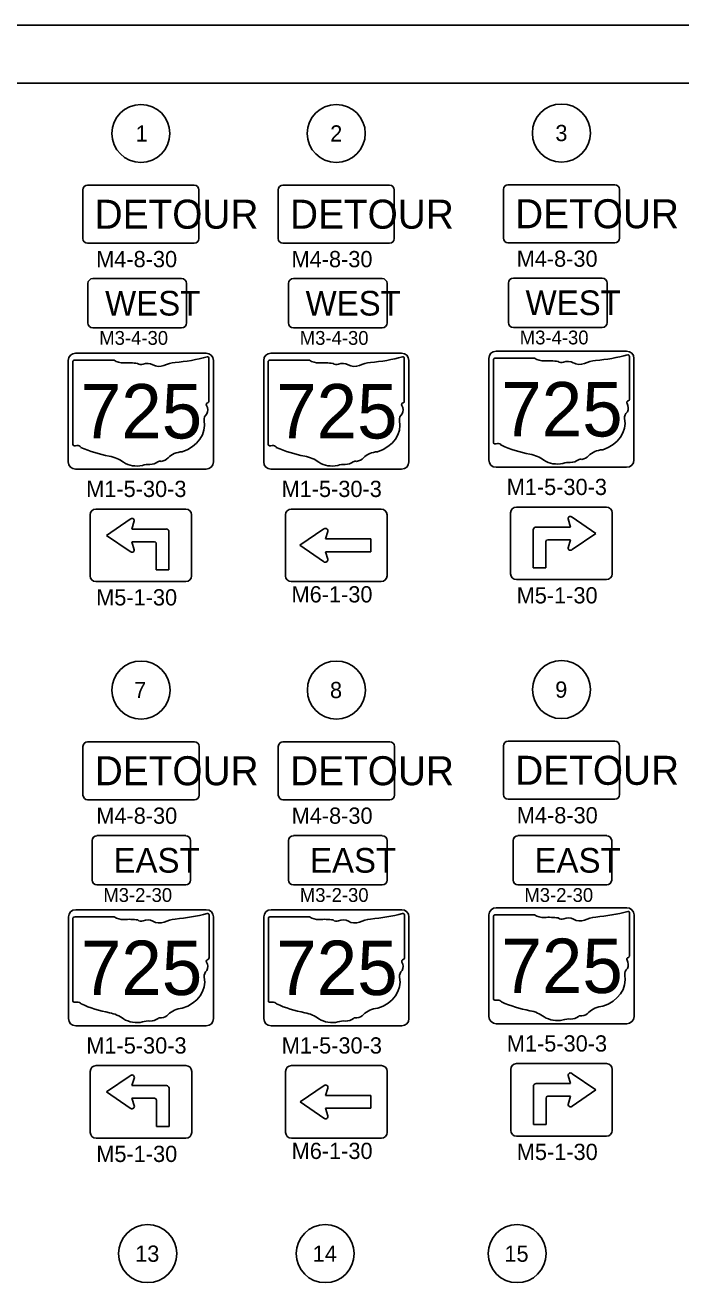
# Model space of a CAD drawing. Extents: x 1341221 to 1914484, y 79347 to 658398.
# Drawn here: x 1435873 to 1461287, y 609451 to 658398 of the extents above; entities that cross this region are included whole.
import ezdxf

# ---------------------------------------------------------------- set-up
doc = ezdxf.new("R2010")
doc.units = 0
for name, color, linetype in [('GM_X_County', 7, 'Continuous'), ('GM_X_County_Road_Text', 7, 'Continuous'), ('GM_X_Minor_Lake_Text', 7, 'Continuous'), ('GM_X_Minor_River', 7, 'Continuous'), ('GM_X_Minor_River_Text', 7, 'Continuous')]:
    doc.layers.add(name, color=color, linetype=linetype)

msp = doc.modelspace()

# ---------------------------------------------------------------- linework, layer by layer
at = {"layer": 'GM_X_County'}
for centre in [(1440356, 654203), (1447931, 654203), (1456659, 654220), (1440361, 632625), (1447935, 632625), (1456664, 632642)]:
    msp.add_circle(centre, 1125, dxfattribs=at)
at = {"layer": 'GM_X_County_Road_Text'}
for centre in [(1440619, 610773), (1447502, 610773), (1454943, 610773)]:
    msp.add_circle(centre, 1125, dxfattribs=at)
at = {"layer": 'GM_X_Minor_Lake_Text'}
msp.add_lwpolyline([(1347971, 656148), (1491971, 656148), (1491971, 561648), (1347971, 561648)], close=True, dxfattribs=at)
at = {"layer": 'GM_X_Minor_River'}
for p, q in [((1438494, 648577), (1441937, 648577)), ((1446268, 648577), (1449710, 648577)), ((1454798, 648594), (1458240, 648594)), ((1438303, 646856), (1438303, 648386)), ((1442128, 648386), (1442128, 646856)), ((1446077, 646856), (1446077, 648386)), ((1449902, 648386), (1449902, 646856)), ((1454606, 646873), (1454606, 648403)), ((1458431, 648403), (1458431, 646873)), ((1441937, 646665), (1438494, 646665)), ((1449710, 646665), (1446268, 646665)), ((1458240, 646682), (1454798, 646682)), ((1437719, 645353), (1437719, 642151)), ((1439315, 645408), (1437771, 645408)), ((1442992, 643813), (1442992, 645488)), ((1445294, 645353), (1445294, 642151)), ((1446890, 645408), (1445346, 645408)), ((1450567, 643813), (1450567, 645488)), ((1454022, 645431), (1454022, 642229)), ((1455618, 645486), (1454074, 645486)), ((1459295, 643890), (1459295, 645565)), ((1442992, 643813), (1442992, 643813)), ((1450566, 643813), (1450567, 643813)), ((1459295, 643891), (1459295, 643890)), ((1438387, 637053), (1438387, 639416)), ((1438612, 639641), (1442099, 639641)), ((1442324, 639416), (1442324, 637053)), ((1445962, 639416), (1445962, 637053)), ((1449674, 639641), (1446187, 639641)), ((1449675, 639641), (1449674, 639641)), ((1449899, 637053), (1449899, 639416)), ((1454690, 639493), (1454690, 637131)), ((1458403, 639718), (1454915, 639718)), ((1457010, 638945), (1456917, 639261)), ((1457077, 639328), (1457995, 638699)), ((1458628, 637131), (1458628, 639493)), ((1439938, 639250), (1439020, 638621)), ((1440004, 638867), (1440098, 639184)), ((1441340, 638867), (1440004, 638867)), ((1441340, 638867), (1441340, 638867)), ((1446524, 638235), (1447455, 638874)), ((1447598, 638769), (1447509, 638481)), ((1455569, 637363), (1455569, 638839)), ((1455674, 638945), (1457010, 638945)), ((1455674, 638945), (1455674, 638945)), ((1439020, 638621), (1439938, 637992)), ((1440098, 638059), (1440004, 638375)), ((1440004, 638375), (1440883, 638375)), ((1440953, 638305), (1440953, 637285)), ((1441446, 637285), (1441446, 638762)), ((1447509, 638481), (1449266, 638481)), ((1449266, 638481), (1449266, 637988)), ((1456061, 638382), (1456061, 637363)), ((1457010, 638452), (1456131, 638452)), ((1456917, 638136), (1457010, 638452)), ((1457995, 638699), (1457077, 638070)), ((1447442, 637606), (1446524, 638235)), ((1449266, 637988), (1447509, 637988)), ((1447509, 637988), (1447598, 637700)), ((1456061, 637363), (1455569, 637363)), ((1442099, 636828), (1438612, 636828)), ((1440953, 637285), (1441446, 637285)), ((1440953, 637285), (1441446, 637285)), ((1446187, 636828), (1449674, 636828)), ((1454915, 636906), (1458403, 636906)), ((1438461, 625258), (1438461, 626788)), ((1438652, 626979), (1442094, 626979)), ((1442286, 626788), (1442286, 625258)), ((1446079, 625258), (1446079, 626788)), ((1446270, 626979), (1449712, 626979)), ((1449904, 626788), (1449904, 625258)), ((1454785, 625258), (1454785, 626788)), ((1454976, 626979), (1458418, 626979)), ((1458610, 626788), (1458610, 625258)), ((1442094, 625066), (1438652, 625066)), ((1449712, 625066), (1446270, 625066)), ((1458418, 625066), (1454976, 625066)), ((1437724, 623776), (1437724, 620574)), ((1439320, 623831), (1437776, 623831)), ((1442997, 622235), (1442997, 623910)), ((1445298, 623776), (1445298, 620574)), ((1446895, 623831), (1445350, 623831)), ((1450572, 622235), (1450572, 623910)), ((1454027, 623853), (1454027, 620651)), ((1455623, 623908), (1454079, 623908)), ((1459300, 622313), (1459300, 623988)), ((1442996, 622235), (1442997, 622235)), ((1450571, 622235), (1450572, 622235)), ((1459300, 622313), (1459300, 622313)), ((1438392, 615476), (1438392, 617838)), ((1438617, 618063), (1442104, 618063)), ((1442329, 617838), (1442329, 615476)), ((1445967, 617838), (1445967, 615476)), ((1449679, 618063), (1446192, 618063)), ((1449679, 618063), (1449679, 618063)), ((1449904, 615476), (1449904, 617838)), ((1454695, 617916), (1454695, 615553)), ((1458408, 618141), (1454920, 618141)), ((1457082, 617750), (1458000, 617121)), ((1458633, 615553), (1458633, 617916)), ((1439943, 617672), (1439025, 617043)), ((1440009, 617289), (1440103, 617606)), ((1441345, 617289), (1440009, 617289)), ((1441345, 617289), (1441345, 617289)), ((1446529, 616657), (1447460, 617297)), ((1455574, 615785), (1455574, 617262)), ((1455679, 617367), (1457015, 617367)), ((1455679, 617367), (1455679, 617367)), ((1457015, 617367), (1456921, 617684)), ((1439025, 617043), (1439943, 616415)), ((1440103, 616481), (1440009, 616797)), ((1440009, 616797), (1440888, 616797)), ((1441451, 615707), (1441451, 617184)), ((1447603, 617192), (1447513, 616903)), ((1447513, 616903), (1449271, 616903)), ((1449271, 616903), (1449271, 616410)), ((1456066, 616805), (1456066, 615785)), ((1457015, 616875), (1456136, 616875)), ((1456921, 616559), (1457015, 616875)), ((1458000, 617121), (1457082, 616492)), ((1440958, 616727), (1440958, 615707)), ((1447447, 616028), (1446529, 616657)), ((1449271, 616410), (1447513, 616410)), ((1447513, 616410), (1447603, 616122)), ((1456066, 615785), (1455574, 615785)), ((1440958, 615707), (1441451, 615707)), ((1440958, 615707), (1441451, 615707)), ((1454920, 615328), (1458408, 615328)), ((1442104, 615251), (1438617, 615251)), ((1446192, 615251), (1449679, 615251))]:
    msp.add_line(p, q, dxfattribs=at)
for points in [[(1438106, 652018), (1438106, 650128)], [(1442426, 652198), (1438286, 652198)], [(1442606, 650128), (1442606, 652018)], [(1445681, 652018), (1445681, 650128)], [(1450001, 652198), (1445861, 652198)], [(1450181, 650128), (1450181, 652018)], [(1454409, 652035), (1454409, 650145)], [(1458729, 652215), (1454589, 652215)], [(1458909, 650145), (1458909, 652035)], [(1438286, 649948), (1442426, 649948)], [(1445861, 649948), (1450001, 649948)], [(1454589, 649965), (1458729, 649965)], [(1437824, 645685), (1442887, 645685)], [(1445399, 645685), (1450462, 645685)], [(1454128, 645762), (1459190, 645762)], [(1437543, 641466), (1437543, 645403)], [(1443168, 645403), (1443168, 641466)], [(1445118, 641466), (1445118, 645403)], [(1450743, 645403), (1450743, 641466)], [(1453846, 641543), (1453846, 645481)], [(1459471, 645481), (1459471, 641543)], [(1459190, 641262), (1454128, 641262)], [(1442887, 641184), (1437824, 641184)], [(1450462, 641184), (1445399, 641184)], [(1442431, 630620), (1438291, 630620)], [(1450005, 630620), (1445865, 630620)], [(1454414, 630458), (1454414, 628568)], [(1458734, 630638), (1454594, 630638)], [(1458914, 628568), (1458914, 630458)], [(1438111, 630440), (1438111, 628550)], [(1442611, 628550), (1442611, 630440)], [(1445685, 630440), (1445685, 628550)], [(1450185, 628550), (1450185, 630440)], [(1438291, 628370), (1442431, 628370)], [(1445865, 628370), (1450005, 628370)], [(1454594, 628388), (1458734, 628388)], [(1437829, 624107), (1442892, 624107)], [(1445404, 624107), (1450467, 624107)], [(1454133, 624184), (1459195, 624184)], [(1437548, 619888), (1437548, 623825)], [(1443173, 623825), (1443173, 619888)], [(1445123, 619888), (1445123, 623825)], [(1450748, 623825), (1450748, 619888)], [(1453851, 619966), (1453851, 623903)], [(1459476, 623903), (1459476, 619966)], [(1459195, 619684), (1454133, 619684)], [(1442892, 619607), (1437829, 619607)], [(1450467, 619607), (1445404, 619607)]]:
    msp.add_lwpolyline(points, dxfattribs=at)
for centre, radius, start, end in [((1438286, 652018), 180, 90, 180), ((1442426, 652018), 180, 0, 90), ((1445861, 652018), 180, 90, 180), ((1450001, 652018), 180, 0, 90), ((1454589, 652035), 180, 90, 180), ((1458729, 652035), 180, 0, 90), ((1438286, 650128), 180, 180, 270), ((1442426, 650128), 180, 270, 0), ((1445861, 650128), 180, 180, 270), ((1450001, 650128), 180, 270, 0), ((1454589, 650145), 180, 180, 270), ((1458729, 650145), 180, 270, 0), ((1438494, 648386), 191, 90, 180), ((1441937, 648386), 191, 0, 90), ((1446268, 648386), 191, 90, 180), ((1449710, 648386), 191, 0, 90), ((1454798, 648403), 191, 90, 180), ((1458240, 648403), 191, 0, 90), ((1438494, 646856), 191, 180, 270), ((1441937, 646856), 191, 270, 0), ((1446268, 646856), 191, 180, 270), ((1449710, 646856), 191, 270, 0), ((1454798, 646873), 191, 180, 270), ((1458240, 646873), 191, 270, 0), ((1437824, 645403), 281, 90, 180), ((1442887, 645403), 281, 0, 90), ((1445399, 645403), 281, 90, 180), ((1450462, 645403), 281, 0, 90), ((1454128, 645481), 281, 90, 180), ((1459190, 645481), 281, 0, 90), ((1437824, 641466), 281, 180, 270), ((1442887, 641466), 281, 270, 0), ((1445399, 641466), 281, 180, 270), ((1450462, 641466), 281, 270, 0), ((1454128, 641543), 281, 180, 270), ((1459190, 641543), 281, 270, 0), ((1438612, 639416), 225, 90, 180), ((1440004, 639184), 93.8, 0.0017, 134.9999), ((1442099, 639416), 225, 0, 90), ((1446187, 639416), 225, 90, 180), ((1449674, 639416), 225, 0, 90), ((1454915, 639493), 225, 90, 180), ((1457010, 639261), 93.8, 45.0001, 179.9983), ((1458403, 639493), 225, 0, 90), ((1441340, 638762), 106, 0, 90), ((1447509, 638797), 93.8, 342.7954, 124.5888), ((1455674, 638839), 106, 90, 180), ((1440883, 638305), 70.2, 0, 90), ((1456132, 638382), 70.2, 90, 180), ((1440004, 638059), 93.8, 225.0001, 0.0017), ((1457010, 638136), 93.8, 179.9983, 314.9999), ((1447509, 637672), 93.8, 224.9904, 17.2046), ((1438612, 637053), 225, 180, 270), ((1442099, 637053), 225, 270, 360), ((1446187, 637053), 225, 180, 270), ((1449674, 637053), 225, 270, 0), ((1454915, 637131), 225, 180, 270), ((1458403, 637131), 225, 270, 0), ((1438291, 630440), 180, 90, 180), ((1442431, 630440), 180, 0, 90), ((1445865, 630440), 180, 90, 180), ((1450005, 630440), 180, 0, 90), ((1454594, 630458), 180, 90, 180), ((1458734, 630458), 180, 0, 90), ((1438291, 628550), 180, 180, 270), ((1442431, 628550), 180, 270, 0), ((1445865, 628550), 180, 180, 270), ((1450005, 628550), 180, 270, 0), ((1454594, 628568), 180, 180, 270), ((1458734, 628568), 180, 270, 0), ((1438652, 626787), 191, 90, 180), ((1442094, 626787), 191, 0, 90), ((1446270, 626787), 191, 90, 180), ((1449712, 626787), 191, 0, 90), ((1454976, 626787), 191, 90, 180), ((1458418, 626787), 191, 0, 90), ((1438652, 625257), 191, 180, 270), ((1442094, 625257), 191, 270, 0), ((1446270, 625257), 191, 180, 270), ((1449712, 625257), 191, 270, 0), ((1454976, 625257), 191, 180, 270), ((1458418, 625257), 191, 270, 0), ((1437829, 623825), 281, 90, 180), ((1442892, 623825), 281, 0, 90), ((1445404, 623825), 281, 90, 180), ((1450467, 623825), 281, 0, 90), ((1454133, 623903), 281, 90, 180), ((1459195, 623903), 281, 0, 90), ((1437829, 619888), 281, 180, 270), ((1442892, 619888), 281, 270, 0), ((1445404, 619888), 281, 180, 270), ((1450467, 619888), 281, 270, 0), ((1454133, 619966), 281, 180, 270), ((1459195, 619966), 281, 270, 0), ((1438617, 617838), 225, 90, 180), ((1442104, 617838), 225, 0, 90), ((1446192, 617838), 225, 90, 180), ((1449679, 617838), 225, 0, 90), ((1454920, 617916), 225, 90, 180), ((1457015, 617684), 93.8, 45.0001, 179.9983), ((1458408, 617916), 225, 0, 90), ((1440009, 617606), 93.8, 0.0017, 134.9999), ((1441345, 617184), 106, 0, 90), ((1447514, 617219), 93.8, 342.7954, 124.5888), ((1455679, 617261), 106, 90, 180), ((1440888, 616727), 70.2, 0, 90), ((1456136, 616804), 70.2, 90, 180), ((1440009, 616481), 93.8, 225.0001, 0.0017), ((1457015, 616559), 93.8, 179.9983, 314.9999), ((1447514, 616094), 93.8, 224.9904, 17.2046), ((1438617, 615476), 225, 180, 270), ((1442104, 615476), 225, 270, 360), ((1446192, 615476), 225, 180, 270), ((1449679, 615476), 225, 270, 0), ((1454920, 615553), 225, 180, 270), ((1458408, 615553), 225, 270, 0)]:
    msp.add_arc(centre, radius, start, end, dxfattribs=at)
for centre, major_axis, start_param, end_param in [((1457417, 649851), (5592, 0), 4.814394, 5.042369), ((1459237, 645572), (58.7, 0), 6.141152, 7.989035), ((1437779, 645360), (61.1, 0), 1.712693, 3.28349), ((1439683, 645780), (593, 0), 4.042523, 4.731795), ((1439879, 643611), (2127, 0), 1.404758, 1.657858), ((1440362, 645377), (171, 0), 3.836095, 5.185415), ((1440613, 645007), (355, 0), 0.950623, 2.079405), ((1441072, 645514), (428, 0), 4.081561, 5.145723), ((1441827, 644430), (1125, 0), 1.699011, 2.107814), ((1441114, 649774), (5592, 0), 4.814394, 5.042369), ((1442934, 645495), (58.7, 0), 6.141152, 7.989035), ((1445354, 645360), (61.1, 0), 1.712693, 3.28349), ((1447258, 645780), (593, 0), 4.042523, 4.731795), ((1447454, 643611), (2127, 0), 1.404758, 1.657858), ((1447937, 645377), (171, 0), 3.836095, 5.185415), ((1448188, 645007), (355, 0), 0.950623, 2.079405), ((1448647, 645514), (428, 0), 4.081561, 5.145723), ((1449402, 644430), (1125, 0), 1.699011, 2.107814), ((1448689, 649774), (5592, 0), 4.814394, 5.042369), ((1450508, 645495), (58.7, 0), 6.141152, 7.989035), ((1454083, 645438), (61.1, 0), 1.712693, 3.28349), ((1455986, 645858), (593, 0), 4.042523, 4.731795), ((1456183, 643688), (2127, 0), 1.404758, 1.657858), ((1456666, 645454), (171, 0), 3.836095, 5.185415), ((1456916, 645084), (355, 0), 0.950623, 2.079405), ((1457375, 645592), (428, 0), 4.081561, 5.145723), ((1458130, 644508), (1125, 0), 1.699011, 2.107814), ((1442979, 643690), (90.9, 0), 1.883978, 3.671073), ((1442930, 643806), (62.8, 0), 5.05454, 6.418171), ((1450553, 643690), (90.9, 0), 1.883978, 3.671073), ((1450504, 643806), (62.8, 0), 5.05454, 6.418171), ((1459282, 643767), (90.9, 0), 1.883978, 3.671073), ((1458704, 643556), (545, 0), 5.934695, 6.695948), ((1459233, 643884), (62.8, 0), 5.05454, 6.418171), ((1443203, 643112), (397, 0), 2.387724, 3.262537), ((1442401, 643478), (545, 0), 5.934695, 6.695948), ((1450777, 643112), (397, 0), 2.387724, 3.262537), ((1449975, 643478), (545, 0), 5.934695, 6.695948), ((1459506, 643190), (397, 0), 2.387724, 3.262537), ((1441427, 642899), (1399, 0), 5.101752, 6.440018), ((1449002, 642899), (1399, 0), 5.101752, 6.440018), ((1457730, 642976), (1399, 0), 5.101752, 6.440018), ((1454083, 642222), (61.6, 0), 3.00124, 4.508301), ((1437780, 642144), (61.6, 0), 3.00124, 4.508301), ((1437789, 642472), (470, 0), 4.665946, 4.897461), ((1437885, 641967), (170, 0), 0.519207, 1.627899), ((1440027, 644843), (4038, 0), 4.195997, 4.488961), ((1442017, 641252), (766, 0), 1.647645, 2.488434), ((1445355, 642144), (61.6, 0), 3.00124, 4.508301), ((1445364, 642472), (470, 0), 4.665946, 4.897461), ((1445460, 641967), (170, 0), 0.519207, 1.627899), ((1447601, 644843), (4038, 0), 4.195997, 4.488961), ((1449592, 641252), (766, 0), 1.647645, 2.488434), ((1454092, 642550), (470, 0), 4.665946, 4.897461), ((1454189, 642044), (170, 0), 0.519207, 1.627899), ((1456330, 644921), (4038, 0), 4.195997, 4.488961), ((1455126, 640791), (1264, 0), 0.823519, 1.323587), ((1457349, 641919), (452, 0), 4.937069, 5.64225), ((1458320, 641330), (766, 0), 1.647645, 2.488434), ((1438823, 640713), (1264, 0), 0.823519, 1.323587), ((1440189, 641951), (802, 0), 4.026481, 4.996735), ((1440652, 640844), (659, 0), 1.495662, 1.94098), ((1440711, 641711), (427, 0), 4.691044, 5.507374), ((1441097, 641401), (120, 0), 1.147584, 2.315152), ((1441046, 641841), (452, 0), 4.937069, 5.64225), ((1446397, 640713), (1264, 0), 0.823519, 1.323587), ((1447764, 641951), (802, 0), 4.026481, 4.996735), ((1448227, 640844), (659, 0), 1.495662, 1.94098), ((1448286, 641711), (427, 0), 4.691044, 5.507374), ((1448672, 641401), (120, 0), 1.147584, 2.315152), ((1448621, 641841), (452, 0), 4.937069, 5.64225), ((1456492, 642028), (802, 0), 4.026481, 4.996735), ((1456956, 640921), (659, 0), 1.495662, 1.94098), ((1457014, 641789), (427, 0), 4.691044, 5.507374), ((1457401, 641479), (120, 0), 1.147584, 2.315152), ((1437784, 623782), (61.1, 0), 1.712693, 3.28349), ((1439688, 624202), (593, 0), 4.042523, 4.731795), ((1439884, 622033), (2127, 0), 1.404758, 1.657858), ((1440367, 623799), (171, 0), 3.836095, 5.185415), ((1440618, 623429), (355, 0), 0.950623, 2.079405), ((1441077, 623936), (428, 0), 4.081561, 5.145723), ((1441832, 622853), (1125, 0), 1.699011, 2.107814), ((1441119, 628196), (5592, 0), 4.814394, 5.042369), ((1442939, 623917), (58.7, 0), 6.141152, 7.989035), ((1445359, 623782), (61.1, 0), 1.712693, 3.28349), ((1447262, 624202), (593, 0), 4.042523, 4.731795), ((1447459, 622033), (2127, 0), 1.404758, 1.657858), ((1447942, 623799), (171, 0), 3.836095, 5.185415), ((1448193, 623429), (355, 0), 0.950623, 2.079405), ((1448652, 623936), (428, 0), 4.081561, 5.145723), ((1449407, 622853), (1125, 0), 1.699011, 2.107814), ((1448693, 628196), (5592, 0), 4.814394, 5.042369), ((1450513, 623917), (58.7, 0), 6.141152, 7.989035), ((1454087, 623860), (61.1, 0), 1.712693, 3.28349), ((1455991, 624280), (593, 0), 4.042523, 4.731795), ((1456187, 622111), (2127, 0), 1.404758, 1.657858), ((1456670, 623877), (171, 0), 3.836095, 5.185415), ((1456921, 623507), (355, 0), 0.950623, 2.079405), ((1457380, 624014), (428, 0), 4.081561, 5.145723), ((1458135, 622930), (1125, 0), 1.699011, 2.107814), ((1457422, 628274), (5592, 0), 4.814394, 5.042369), ((1459242, 623995), (58.7, 0), 6.141152, 7.989035), ((1442983, 622112), (90.9, 0), 1.883978, 3.671073), ((1442934, 622229), (62.8, 0), 5.05454, 6.418171), ((1450558, 622112), (90.9, 0), 1.883978, 3.671073), ((1450509, 622229), (62.8, 0), 5.05454, 6.418171), ((1459287, 622190), (90.9, 0), 1.883978, 3.671073), ((1458709, 621978), (545, 0), 5.934695, 6.695948), ((1459238, 622306), (62.8, 0), 5.05454, 6.418171), ((1443207, 621534), (397, 0), 2.387724, 3.262537), ((1442405, 621900), (545, 0), 5.934695, 6.695948), ((1450782, 621534), (397, 0), 2.387724, 3.262537), ((1449980, 621900), (545, 0), 5.934695, 6.695948), ((1459511, 621612), (397, 0), 2.387724, 3.262537), ((1441432, 621321), (1399, 0), 5.101752, 6.440018), ((1449007, 621321), (1399, 0), 5.101752, 6.440018), ((1457735, 621399), (1399, 0), 5.101752, 6.440018), ((1437785, 620567), (61.6, 0), 3.00124, 4.508301), ((1437794, 620894), (470, 0), 4.665946, 4.897461), ((1437890, 620389), (170, 0), 0.519207, 1.627899), ((1440031, 623266), (4038, 0), 4.195997, 4.488961), ((1442022, 619675), (766, 0), 1.647645, 2.488434), ((1445359, 620567), (61.6, 0), 3.00124, 4.508301), ((1445369, 620894), (470, 0), 4.665946, 4.897461), ((1445465, 620389), (170, 0), 0.519207, 1.627899), ((1447606, 623266), (4038, 0), 4.195997, 4.488961), ((1449596, 619675), (766, 0), 1.647645, 2.488434), ((1454088, 620644), (61.6, 0), 3.00124, 4.508301), ((1454097, 620972), (470, 0), 4.665946, 4.897461), ((1454193, 620467), (170, 0), 0.519207, 1.627899), ((1456335, 623343), (4038, 0), 4.195997, 4.488961), ((1455131, 619213), (1264, 0), 0.823519, 1.323587), ((1458325, 619752), (766, 0), 1.647645, 2.488434), ((1438827, 619135), (1264, 0), 0.823519, 1.323587), ((1440194, 620373), (802, 0), 4.026481, 4.996735), ((1440657, 619266), (659, 0), 1.495662, 1.94098), ((1440716, 620133), (427, 0), 4.691044, 5.507374), ((1441102, 619823), (120, 0), 1.147584, 2.315152), ((1441051, 620263), (452, 0), 4.937069, 5.64225), ((1446402, 619135), (1264, 0), 0.823519, 1.323587), ((1447769, 620373), (802, 0), 4.026481, 4.996735), ((1448232, 619266), (659, 0), 1.495662, 1.94098), ((1448291, 620133), (427, 0), 4.691044, 5.507374), ((1448677, 619823), (120, 0), 1.147584, 2.315152), ((1448626, 620263), (452, 0), 4.937069, 5.64225), ((1456497, 620451), (802, 0), 4.026481, 4.996735), ((1456961, 619344), (659, 0), 1.495662, 1.94098), ((1457019, 620211), (427, 0), 4.691044, 5.507374), ((1457406, 619901), (120, 0), 1.147584, 2.315152), ((1457354, 620341), (452, 0), 4.937069, 5.64225)]:
    msp.add_ellipse(centre, major_axis=major_axis, ratio=0.8, start_param=start_param, end_param=end_param, dxfattribs=at)
at = {"layer": 'GM_X_Minor_River_Text'}
msp.add_lwpolyline([(1341221, 559398), (1494221, 559398), (1494221, 658398), (1341221, 658398)], close=True, dxfattribs=at)

# ---------------------------------------------------------------- texts
at = {"layer": 'GM_X_County'}
for s, p in [('1', (1440150, 653888)), ('2', (1447695, 653888)), ('3', (1456426, 653905)), ('7', (1440095, 632310)), ('8', (1447688, 632310)), ('9', (1456420, 632327))]:
    msp.add_text(s, height=630, dxfattribs=at).set_placement(p)
at = {"layer": 'GM_X_County_Road_Text'}
for s, height, p in [('M4-8-30', 630, (1438623, 649017)), ('M4-8-30', 630, (1446198, 649017)), ('M4-8-30', 630, (1454926, 649034)), ('M3-4-30', 535.5, (1438743, 646008)), ('M3-4-30', 535.5, (1446516, 646008)), ('M3-4-30', 535.5, (1455046, 646025)), ('M1-5-30-3', 630, (1438236, 640108)), ('M1-5-30-3', 630, (1445811, 640108)), ('M1-5-30-3', 630, (1454539, 640185)), ('M5-1-30', 630, (1438623, 635904)), ('M6-1-30', 630, (1446198, 636021)), ('M5-1-30', 630, (1454926, 635982)), ('M4-8-30', 630, (1438628, 627439)), ('M4-8-30', 630, (1446202, 627439)), ('M4-8-30', 630, (1454931, 627456)), ('M3-2-30', 535.5, (1438900, 624410)), ('M3-2-30', 535.5, (1446518, 624410)), ('M3-2-30', 535.5, (1455224, 624410)), ('M1-5-30-3', 630, (1454544, 618608)), ('M1-5-30-3', 630, (1438241, 618530)), ('M1-5-30-3', 630, (1445816, 618530)), ('M5-1-30', 630, (1438628, 614326)), ('M6-1-30', 630, (1446202, 614443)), ('M5-1-30', 630, (1454931, 614404)), ('13', 630, (1440134, 610458)), ('14', 630, (1447017, 610458)), ('15', 630, (1454451, 610458))]:
    msp.add_text(s, height=height, dxfattribs=at).set_placement(p)
at = {"layer": 'GM_X_Minor_River'}
for s, height, p in [('DETOUR', 1125, (1438563, 650511)), ('DETOUR', 1125, (1446138, 650511)), ('DETOUR', 1125, (1454866, 650528)), ('WEST', 956.2, (1438968, 647143)), ('WEST', 956.2, (1446741, 647143)), ('WEST', 956.2, (1455271, 647160)), ('725', 2109.4, (1438025, 642377)), ('725', 2109.4, (1445599, 642377)), ('725', 2109.4, (1454328, 642455)), ('DETOUR', 1125, (1438568, 628933)), ('DETOUR', 1125, (1446143, 628933)), ('DETOUR', 1125, (1454871, 628950)), ('EAST', 956.2, (1439295, 625544)), ('EAST', 956.2, (1446912, 625544)), ('EAST', 956.2, (1455618, 625544)), ('725', 2109.4, (1438029, 620799)), ('725', 2109.4, (1445604, 620799)), ('725', 2109.4, (1454333, 620877))]:
    msp.add_text(s, height=height, dxfattribs=at).set_placement(p)

doc.saveas('drawing.dxf')
